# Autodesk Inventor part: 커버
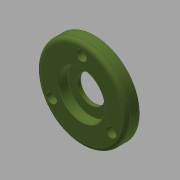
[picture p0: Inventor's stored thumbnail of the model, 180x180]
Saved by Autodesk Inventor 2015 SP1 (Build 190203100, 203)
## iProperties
Created: 2016-06
Part Number: 커버
Material: 알루미늄 6061
Document SubType Name: Modeling
Designer: mduedu
Density: 2.71 g/cm^3
Appearance: 올리브 녹색
Author: mduedu
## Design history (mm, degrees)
sketch "스케치1"
  geometry: C1 r 34 at (0, 0); 1 further point
  constraints: 1 centre point, 1 coincident
  dimensions: "d0" = 68 diameter of C1
extrude "돌출1" new body sketch "스케치1" distance "d2" = 10; taper "d3" = 0 deg
sketch "스케치2"
  geometry: C1 r 21 at (0, 0); 1 further point
  constraints: 1 centre point, 1 coincident
  dimensions: "d4" = 42 diameter of C1
extrude "돌출2" join sketch "스케치2" distance "d6" = 3; taper "d7" = 0 deg
fillet "모깎기1" dims "d8" = 3
hole "구멍1" diameter "d11" = 35; stored, may be unused: countersink angle "d15" = 90 deg, drill point angle "d17" = 0 deg; dims "d9" = 10, "d10" = 10, "d12" = 6, "d13" = 4, "d14" = 2, "d16" = 3
hole "구멍2" diameter "d20" = 35; stored, may be unused: countersink angle "d24" = 90 deg, drill point angle "d26" = 0 deg; dims "d21" = 6, "d22" = 4, "d23" = 2, "d25" = 7.3, "d73" = 10, "d74" = 10
hole "구멍3" diameter "d29" = 21; stored, may be unused: countersink angle "d33" = 90 deg, drill point angle "d35" = 0 deg; dims "d27" = 10, "d28" = 10, "d30" = 6, "d31" = 4, "d32" = 2, "d34" = 5
fillet "모깎기2" dims "d36" = 3
fillet "모깎기3" dims "d37" = 0.1
chamfer "모따기1" distance "d38" = 0.7; stored, may be unused: second distance "d39" = 2, angle "d40" = 30 deg
chamfer "모따기2" distance "d42" = 0.5; stored, may be unused: second distance "d43" = 2, angle "d44" = 30 deg
sketch "스케치5" dims "d60" = 52
  geometry: 3 further points
  constraints: 2 vertical alignment, 1 coincident, 2 other
hole "구멍5" sketch "스케치5" at (0, 26) diameter "d61" = 4.5; stored, may be unused: countersink angle "d65" = 90 deg, drill point angle "d67" = 118 deg; dims "d62" = 6, "d63" = 8, "d64" = 4.6, "d66" = 8
node "솔리드1"
pattern_circular "원형 패턴1" dims angle "d69" = 360 deg
